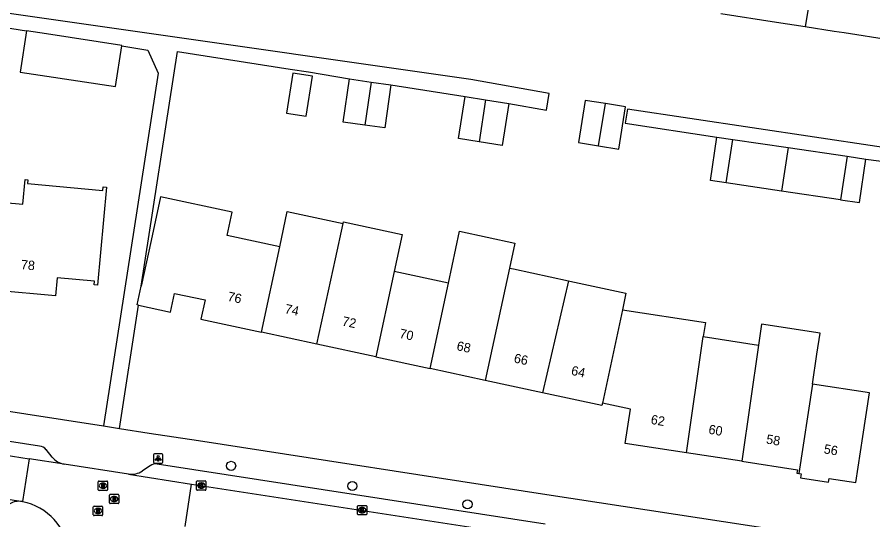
# Model space of a CAD drawing. Extents: x 161486 to 162249, y 379484 to 380829.
# Drawn here: x 161831.1 to 161923, y 380555.5 to 380609.4 of the extents above; entities that cross this region are included whole.
import ezdxf

# ---------------------------------------------------------------- set-up
doc = ezdxf.new("R2010")
doc.units = 0
for name, color, linetype in [('IMGEO_Boom', 7, 'Continuous'), ('IMGEO_Kolk', 7, 'Continuous'), ('IMGEO_Lichtpunt', 7, 'Continuous'), ('IMGEO_Pand', 7, 'Continuous'), ('IMGEO_Pand_nummerreeks', 7, 'Continuous'), ('IMGEO_Rijbaan_lokaal_open', 7, 'Continuous'), ('IMGEO_Rioolput', 7, 'Continuous'), ('IMGEO_Voetpad_open', 7, 'Continuous')]:
    doc.layers.add(name, color=color, linetype=linetype)

msp = doc.modelspace()

# ---------------------------------------------------------------- linework, layer by layer
at = {"layer": 'IMGEO_Boom'}
for centre in [(161854.107, 380561.287), (161867.109, 380559.125), (161879.472, 380557.176)]:
    msp.add_circle(centre, 0.489, dxfattribs=at)
at = {"layer": 'IMGEO_Kolk'}
for p, q in [((161850.484, 380559.678), (161851.336, 380559.678)), ((161850.409, 380558.752), (161850.409, 380559.604)), ((161850.92, 380558.898), (161850.895, 380558.898)), ((161850.897, 380559.458), (161850.922, 380559.458)), ((161851.41, 380559.604), (161851.41, 380558.752)), ((161851.336, 380558.678), (161850.484, 380558.678)), ((161867.662, 380556.114), (161867.662, 380556.966)), ((161867.737, 380557.04), (161868.589, 380557.04)), ((161868.663, 380556.966), (161868.663, 380556.114)), ((161868.589, 380556.04), (161867.737, 380556.04)), ((161868.173, 380556.26), (161868.148, 380556.26)), ((161868.15, 380556.82), (161868.175, 380556.82))]:
    msp.add_line(p, q, dxfattribs=at)
for points in [[(161850.484, 380559.678), (161851.336, 380559.678)], [(161850.409, 380558.752), (161850.409, 380559.604)], [(161850.73, 380559.378), (161850.853, 380559.378), (161850.853, 380559.227), (161850.983, 380559.378), (161851.147, 380559.378), (161851.001, 380559.227), (161851.154, 380558.978), (161851.002, 380558.978), (161850.917, 380559.142), (161850.853, 380559.075), (161850.853, 380558.978), (161850.73, 380558.978), (161850.73, 380559.378)], [(161851.41, 380559.604), (161851.41, 380558.752)], [(161851.336, 380558.678), (161850.484, 380558.678)], [(161867.662, 380556.114), (161867.662, 380556.966)], [(161867.737, 380557.04), (161868.589, 380557.04)], [(161868.663, 380556.966), (161868.663, 380556.114)], [(161868.589, 380556.04), (161867.737, 380556.04)], [(161867.983, 380556.74), (161868.106, 380556.74), (161868.106, 380556.589), (161868.236, 380556.74), (161868.4, 380556.74), (161868.254, 380556.589), (161868.407, 380556.34), (161868.255, 380556.34), (161868.17, 380556.504), (161868.106, 380556.437), (161868.106, 380556.34), (161867.983, 380556.34), (161867.983, 380556.74)]]:
    msp.add_lwpolyline(points, dxfattribs=at)
for centre, start, end in [((161850.486, 380559.602), 91.55205, 178.44795), ((161850.486, 380559.602), 91.55205, 178.44795), ((161851.334, 380559.602), 1.55205, 88.44795), ((161851.334, 380559.602), 1.55205, 88.44795), ((161850.486, 380558.754), 181.55205, 268.44795), ((161850.486, 380558.754), 181.55205, 268.44795), ((161851.334, 380558.754), 271.55205, 358.44795), ((161851.334, 380558.754), 271.55205, 358.44795), ((161867.739, 380556.964), 91.55205, 178.44795), ((161867.739, 380556.964), 91.55205, 178.44795), ((161868.587, 380556.964), 1.55205, 88.44795), ((161868.587, 380556.964), 1.55205, 88.44795), ((161867.739, 380556.116), 181.55205, 268.44795), ((161867.739, 380556.116), 181.55205, 268.44795), ((161868.587, 380556.116), 271.55205, 358.44795), ((161868.587, 380556.116), 271.55205, 358.44795)]:
    msp.add_arc(centre, 0.0765, start, end, dxfattribs=at)
for centre, major_axis, ratio, start_param, end_param in [((161850.896, 380559.178), (-0.387, 0.002), 0.722429, 4.712389, 7.853982), ((161850.921, 380559.178), (-0.39, 0.002), 0.717154, 1.570796, 4.712389), ((161868.149, 380556.54), (-0.387, 0.002), 0.722429, 4.712389, 7.853982), ((161868.174, 380556.54), (-0.39, 0.002), 0.717154, 1.570796, 4.712389)]:
    msp.add_ellipse(centre, major_axis=major_axis, ratio=ratio, start_param=start_param, end_param=end_param, dxfattribs=at)
at = {"layer": 'IMGEO_Lichtpunt'}
for p, q in [((161845.782, 380562.487), (161845.782, 380561.68)), ((161845.782, 380562.487), (161845.782, 380561.68)), ((161846.684, 380562.582), (161845.876, 380562.582)), ((161846.684, 380562.582), (161845.876, 380562.582)), ((161846.778, 380561.68), (161846.778, 380562.487)), ((161846.778, 380561.68), (161846.778, 380562.487)), ((161845.876, 380561.586), (161846.684, 380561.586)), ((161845.876, 380561.586), (161846.684, 380561.586))]:
    msp.add_line(p, q, dxfattribs=at)
for points in [[(161846.156, 380562.151), (161846.195, 380562.123), (161846.007, 380561.861), (161845.969, 380561.888), (161846.156, 380562.151)], [(161846.258, 380562.103), (161846.305, 380562.103), (161846.305, 380561.781), (161846.258, 380561.781), (161846.258, 380562.103)], [(161846.368, 380562.123), (161846.406, 380562.15), (161846.593, 380561.888), (161846.554, 380561.86), (161846.368, 380562.123)]]:
    msp.add_lwpolyline(points, dxfattribs=at)
msp.add_circle((161846.281, 380562.285), 0.0994, dxfattribs=at)
for centre, start, end in [((161845.876, 380562.487), 90, 180), ((161845.876, 380562.487), 90, 180), ((161846.684, 380562.487), 0, 90), ((161846.684, 380562.487), 0, 90), ((161845.876, 380561.68), 180, 270), ((161845.876, 380561.68), 180, 270), ((161846.684, 380561.68), 270, 0), ((161846.684, 380561.68), 270, 360)]:
    msp.add_arc(centre, 0.0946, start, end, dxfattribs=at)
at = {"layer": 'IMGEO_Pand'}
for points in [[(161917.716, 380621.282), (161923.826, 380620.34), (161923.776, 380620.014), (161923.448, 380620.062), (161922.489, 380614.014), (161925.86, 380613.48), (161924.84, 380606.93), (161919.899, 380607.691), (161918.824, 380607.857), (161915.718, 380608.336)], [(161917.716, 380621.282), (161916.158, 380611.186), (161915.718, 380608.336)], [(161915.718, 380608.336), (161912.612, 380608.815), (161906.646, 380609.735)], [(161832.16, 380607.936), (161831.481, 380603.508), (161833.607, 380603.182), (161841.714, 380601.939), (161842.385, 380606.316)], [(161842.385, 380606.316), (161842.393, 380606.367), (161834.286, 380607.61), (161832.16, 380607.936)], [(161862.174, 380598.776), (161862.854, 380603.062), (161860.742, 380603.397), (161860.062, 380599.111), (161862.174, 380598.776)], [(161868.445, 380597.821), (161866.145, 380598.149), (161866.804, 380602.759)], [(161866.804, 380602.759), (161869.142, 380602.425)], [(161869.142, 380602.425), (161868.445, 380597.821)], [(161871.255, 380602.123), (161870.597, 380597.514), (161868.445, 380597.821)], [(161869.142, 380602.425), (161871.255, 380602.123)], [(161880.721, 380596.031), (161878.51, 380596.383), (161879.224, 380600.868)], [(161879.224, 380600.868), (161881.401, 380600.521)], [(161881.401, 380600.521), (161880.721, 380596.031)], [(161883.887, 380600.126), (161883.173, 380595.641), (161880.721, 380596.031)], [(161881.401, 380600.521), (161883.887, 380600.126)], [(161894.269, 380600.119), (161892.108, 380600.468), (161891.377, 380595.94), (161893.538, 380595.591)], [(161893.538, 380595.591), (161894.269, 380600.119)], [(161893.538, 380595.591), (161895.698, 380595.242), (161896.429, 380599.77), (161894.269, 380600.119)], [(161907.228, 380591.616), (161905.531, 380591.864), (161906.212, 380596.519)], [(161906.212, 380596.519), (161907.933, 380596.268)], [(161907.228, 380591.616), (161907.933, 380596.268)], [(161907.933, 380596.268), (161913.867, 380595.4)], [(161913.867, 380595.4), (161913.174, 380590.746)], [(161913.867, 380595.4), (161920.206, 380594.472)], [(161920.206, 380594.472), (161919.495, 380589.821)], [(161919.495, 380589.821), (161921.545, 380589.521), (161922.227, 380594.176)], [(161920.206, 380594.472), (161922.227, 380594.176)], [(161829.752, 380589.535), (161831.766, 380589.35), (161832.008, 380591.981), (161832.306, 380591.954), (161832.27, 380591.555), (161840.35, 380590.812), (161840.386, 380591.21), (161840.745, 380591.177), (161839.777, 380580.662), (161839.419, 380580.695), (161839.455, 380581.088), (161835.427, 380581.459), (161835.248, 380579.514), (161828.883, 380580.1)], [(161913.174, 380590.746), (161907.228, 380591.616)], [(161859.317, 380584.764), (161853.676, 380585.979), (161854.213, 380588.471), (161846.529, 380590.126), (161845.518, 380585.433), (161844.465, 380580.545)], [(161919.495, 380589.821), (161913.174, 380590.746)], [(161859.317, 380584.764), (161860.136, 380588.564), (161866.129, 380587.273)], [(161863.308, 380574.344), (161865.301, 380583.475), (161866.129, 380587.273)], [(161866.129, 380587.273), (161866.164, 380587.432), (161872.458, 380586.077), (161871.605, 380582.117)], [(161877.415, 380580.866), (161878.615, 380586.438), (161884.547, 380585.161), (161883.971, 380582.483)], [(161857.349, 380575.628), (161859.317, 380584.764)], [(161871.605, 380582.117), (161869.638, 380572.981)], [(161877.415, 380580.866), (161871.605, 380582.117)], [(161883.971, 380582.483), (161881.377, 380570.452)], [(161883.971, 380582.483), (161884.39, 380582.393), (161890.304, 380581.119)], [(161875.476, 380571.723), (161877.415, 380580.866)], [(161890.304, 380581.119), (161887.511, 380569.131)], [(161890.304, 380581.119), (161890.462, 380581.085), (161896.472, 380579.79), (161896.089, 380578.009)], [(161844.153, 380578.524), (161844.035, 380578.549), (161844.465, 380580.545)], [(161844.153, 380578.524), (161847.611, 380577.779), (161848.041, 380579.775), (161851.308, 380579.071), (161850.867, 380577.024), (161857.349, 380575.628)], [(161896.089, 380578.009), (161893.937, 380568.018)], [(161896.089, 380578.009), (161904.995, 380576.648), (161904.771, 380575.144)], [(161916.475, 380570.046), (161916.969, 380573.28), (161917.312, 380575.528), (161911.019, 380576.489), (161910.697, 380574.238)], [(161863.308, 380574.344), (161857.349, 380575.628)], [(161902.969, 380562.694), (161904.771, 380575.144)], [(161904.771, 380575.144), (161910.697, 380574.238)], [(161869.638, 380572.981), (161863.308, 380574.344)], [(161910.697, 380574.238), (161908.915, 380561.786)], [(161869.638, 380572.981), (161875.476, 380571.723)], [(161881.377, 380570.452), (161875.476, 380571.723)], [(161887.511, 380569.131), (161881.377, 380570.452)], [(161915.011, 380560.46), (161915.269, 380560.421), (161915.204, 380559.997), (161918.204, 380559.538), (161918.264, 380559.931), (161921.134, 380559.493), (161921.89, 380564.436), (161922.604, 380569.109), (161916.475, 380570.046)], [(161916.475, 380570.046), (161915.011, 380560.46)], [(161893.937, 380568.018), (161893.881, 380567.759), (161887.511, 380569.131)], [(161902.969, 380562.694), (161896.392, 380563.699), (161896.948, 380567.369), (161893.937, 380568.018)], [(161908.915, 380561.786), (161902.969, 380562.694)], [(161908.915, 380561.786), (161914.881, 380560.874), (161914.822, 380560.489), (161915.011, 380560.46)]]:
    msp.add_lwpolyline(points, dxfattribs=at)
at = {"layer": 'IMGEO_Rijbaan_lokaal_open'}
for points in [[(161831.511, 380557.484), (161829.252, 380557.84), (161786.826, 380564.413), (161764.174, 380567.941)], [(161791.712, 380568.325), (161795.116, 380567.782), (161814.963, 380564.744), (161829.769, 380562.474), (161832.422, 380562.046)], [(161832.422, 380562.046), (161831.714, 380557.452)], [(161836.189, 380561.463), (161832.422, 380562.046)], [(161843.094, 380560.41), (161836.189, 380561.463)], [(161843.094, 380560.41), (161849.846, 380559.342)], [(161849.159, 380554.782), (161849.846, 380559.342)], [(161849.846, 380559.342), (161887.499, 380553.536), (161890.424, 380553.087)], [(161831.714, 380557.452), (161831.511, 380557.484)]]:
    msp.add_lwpolyline(points, dxfattribs=at)
msp.add_arc((161830.522, 380551.353), 6.214, 5.48219, 78.94489, dxfattribs=at)
at = {"layer": 'IMGEO_Rioolput'}
for p, q in [((161839.856, 380558.733), (161839.856, 380559.585)), ((161839.931, 380559.659), (161840.783, 380559.659)), ((161840.367, 380558.879), (161840.342, 380558.879)), ((161840.344, 380559.439), (161840.369, 380559.439)), ((161840.857, 380559.585), (161840.857, 380558.733)), ((161840.783, 380558.659), (161839.931, 380558.659)), ((161841.06, 380557.312), (161841.06, 380558.164)), ((161841.135, 380558.238), (161841.987, 380558.238)), ((161841.548, 380558.018), (161841.573, 380558.018)), ((161842.061, 380558.164), (161842.061, 380557.312)), ((161839.397, 380556.964), (161840.249, 380556.964)), ((161841.987, 380557.238), (161841.135, 380557.238)), ((161841.571, 380557.458), (161841.546, 380557.458)), ((161839.322, 380556.038), (161839.322, 380556.89)), ((161839.833, 380556.184), (161839.808, 380556.184)), ((161839.81, 380556.744), (161839.835, 380556.744)), ((161840.323, 380556.89), (161840.323, 380556.038)), ((161840.249, 380555.964), (161839.397, 380555.964))]:
    msp.add_line(p, q, dxfattribs=at)
for points in [[(161839.856, 380558.733), (161839.856, 380559.585)], [(161839.931, 380559.659), (161840.783, 380559.659)], [(161840.445, 380559.357), (161840.193, 380559.359), (161840.193, 380558.959)], [(161840.193, 380558.959), (161840.317, 380558.959), (161840.317, 380559.121), (161840.328, 380559.121)], [(161840.371, 380559.278), (161840.317, 380559.278), (161840.317, 380559.197)], [(161840.317, 380559.197), (161840.369, 380559.197)], [(161840.375, 380559.092), (161840.446, 380558.959), (161840.586, 380558.959), (161840.521, 380559.085)], [(161840.857, 380559.585), (161840.857, 380558.733)], [(161840.783, 380558.659), (161839.931, 380558.659)], [(161841.06, 380557.312), (161841.06, 380558.164)], [(161841.135, 380558.238), (161841.987, 380558.238)], [(161841.649, 380557.936), (161841.397, 380557.938), (161841.397, 380557.538)], [(161841.575, 380557.857), (161841.521, 380557.857), (161841.521, 380557.776)], [(161842.061, 380558.164), (161842.061, 380557.312)], [(161839.397, 380556.964), (161840.249, 380556.964)], [(161841.987, 380557.238), (161841.135, 380557.238)], [(161841.397, 380557.538), (161841.521, 380557.538), (161841.521, 380557.7), (161841.532, 380557.7)], [(161841.521, 380557.776), (161841.573, 380557.776)], [(161841.579, 380557.671), (161841.65, 380557.538), (161841.79, 380557.538), (161841.725, 380557.664)], [(161839.322, 380556.038), (161839.322, 380556.89)], [(161839.911, 380556.662), (161839.659, 380556.664), (161839.659, 380556.264)], [(161839.659, 380556.264), (161839.783, 380556.264), (161839.783, 380556.426), (161839.794, 380556.426)], [(161839.837, 380556.583), (161839.783, 380556.583), (161839.783, 380556.502)], [(161839.783, 380556.502), (161839.835, 380556.502)], [(161839.841, 380556.397), (161839.912, 380556.264), (161840.052, 380556.264), (161839.987, 380556.39)], [(161840.323, 380556.89), (161840.323, 380556.038)], [(161840.249, 380555.964), (161839.397, 380555.964)]]:
    msp.add_lwpolyline(points, dxfattribs=at)
for centre, radius, start, end in [((161839.933, 380559.583), 0.0765, 91.55205, 178.44795), ((161839.933, 380559.583), 0.0765, 91.55205, 178.44795), ((161840.327, 380559.068), 0.0533, 26.02933, 88.69889), ((161840.353, 380559.386), 0.19, 274.7715, 282.96867), ((161840.377, 380559.182), 0.0964, 77.00612, 93.18647), ((161840.391, 380559.239), 0.0378, 276.66336, 79.67722), ((161840.444, 380559.247), 0.109, 350.36119, 89.41601), ((161840.442, 380559.247), 0.112, 277.58423, 350.98172), ((161840.426, 380559.032), 0.108, 29.51342, 73.79051), ((161840.781, 380559.583), 0.0765, 1.55205, 88.44795), ((161840.781, 380559.583), 0.0765, 1.55205, 88.44795), ((161839.933, 380558.735), 0.0765, 181.55205, 268.44795), ((161839.933, 380558.735), 0.0765, 181.55205, 268.44795), ((161840.781, 380558.735), 0.0765, 271.55205, 358.44795), ((161840.781, 380558.735), 0.0765, 271.55205, 358.44795), ((161841.137, 380558.162), 0.0765, 91.55205, 178.44795), ((161841.137, 380558.162), 0.0765, 91.55205, 178.44795), ((161841.581, 380557.761), 0.0964, 77.00612, 93.18647), ((161841.595, 380557.818), 0.0378, 276.66336, 79.67722), ((161841.648, 380557.826), 0.109, 350.36119, 89.41601), ((161841.985, 380558.162), 0.0765, 1.55205, 88.44795), ((161841.985, 380558.162), 0.0765, 1.55205, 88.44795), ((161839.399, 380556.888), 0.0765, 91.55205, 178.44795), ((161839.399, 380556.888), 0.0765, 91.55205, 178.44795), ((161840.247, 380556.888), 0.0765, 1.55205, 88.44795), ((161840.247, 380556.888), 0.0765, 1.55205, 88.44795), ((161841.137, 380557.314), 0.0765, 181.55205, 268.44795), ((161841.137, 380557.314), 0.0765, 181.55205, 268.44795), ((161841.531, 380557.647), 0.0533, 26.02933, 88.69889), ((161841.557, 380557.965), 0.19, 274.7715, 282.96867), ((161841.646, 380557.826), 0.112, 277.58423, 350.98172), ((161841.63, 380557.611), 0.108, 29.51342, 73.79051), ((161841.985, 380557.314), 0.0765, 271.55205, 358.44795), ((161841.985, 380557.314), 0.0765, 271.55205, 358.44795), ((161839.399, 380556.04), 0.0765, 181.55205, 268.44795), ((161839.399, 380556.04), 0.0765, 181.55205, 268.44795), ((161839.793, 380556.373), 0.0533, 26.02933, 88.69889), ((161839.819, 380556.691), 0.19, 274.7715, 282.96867), ((161839.843, 380556.487), 0.0964, 77.00612, 93.18647), ((161839.857, 380556.544), 0.0378, 276.66336, 79.67722), ((161839.91, 380556.552), 0.109, 350.36119, 89.41601), ((161839.908, 380556.552), 0.112, 277.58423, 350.98172), ((161839.892, 380556.337), 0.108, 29.51342, 73.79051), ((161840.247, 380556.04), 0.0765, 271.55205, 358.44795), ((161840.247, 380556.04), 0.0765, 271.55205, 358.44795)]:
    msp.add_arc(centre, radius, start, end, dxfattribs=at)
for centre, major_axis, ratio, start_param, end_param in [((161840.343, 380559.159), (-0.387, 0.002), 0.722429, 4.712389, 7.853982), ((161840.368, 380559.159), (-0.39, 0.002), 0.717154, 1.570796, 4.712389), ((161841.547, 380557.738), (-0.387, 0.002), 0.722429, 4.712389, 7.853982), ((161841.572, 380557.738), (-0.39, 0.002), 0.717154, 1.570796, 4.712389), ((161839.809, 380556.464), (-0.387, 0.002), 0.722429, 4.712389, 7.853982), ((161839.834, 380556.464), (-0.39, 0.002), 0.717154, 1.570796, 4.712389)]:
    msp.add_ellipse(centre, major_axis=major_axis, ratio=ratio, start_param=start_param, end_param=end_param, dxfattribs=at)
at = {"layer": 'IMGEO_Voetpad_open'}
for points in [[(161883.887, 380600.126), (161887.936, 380599.416), (161888.243, 380601.193), (161879.814, 380602.708), (161803.016, 380613.72)], [(161827.864, 380608.608), (161832.16, 380607.936)], [(161842.385, 380606.316), (161845.162, 380605.856), (161846.266, 380603.381), (161840.43, 380565.564)], [(161844.465, 380580.545), (161848.361, 380605.693), (161860.44, 380603.822), (161862.401, 380603.511), (161866.804, 380602.759)], [(161871.255, 380602.123), (161879.224, 380600.868)], [(161930.073, 380594.51), (161896.647, 380599.526), (161896.401, 380598.035), (161906.212, 380596.519)], [(161922.227, 380594.176), (161923.617, 380593.973), (161926.255, 380593.587)], [(161759.209, 380578.08), (161759.686, 380578.007), (161785.522, 380574.037), (161840.43, 380565.564)], [(161842.113, 380565.304), (161844.153, 380578.524)], [(161833.563, 380563.394), (161794.647, 380569.433)], [(161840.43, 380565.564), (161842.113, 380565.304)], [(161842.113, 380565.304), (161845.302, 380564.812), (161850.616, 380563.993), (161887.994, 380558.235), (161920.738, 380553.21), (161923.744, 380552.759)], [(161834.914, 380562.21), (161834.252, 380563.026)], [(161845.417, 380561.299), (161844.603, 380560.74)], [(161887.795, 380555.038), (161850.1, 380560.875), (161846.172, 380561.483)]]:
    msp.add_lwpolyline(points, dxfattribs=at)
for centre, radius, start, end in [((161833.506, 380562.458), 0.937, 37.27058, 86.51541), ((161836.574, 380563.582), 2.154, 219.57402, 259.69541), ((161843.399, 380562.631), 2.242, 262.18811, 302.48327), ((161846.005, 380560.529), 0.968, 80.04035, 127.35261), ((161831.319, 380555.611), 1.882, 84.15465, 126.22171)]:
    msp.add_arc(centre, radius, start, end, dxfattribs=at)

# ---------------------------------------------------------------- texts
at = {"layer": 'IMGEO_Pand_nummerreeks'}
for s, rotation, p in [('78', 354.74025, (161831.523, 380582.386)), ('76', 347.84184, (161853.662, 380579)), ('74', 347.84184, (161859.807, 380577.677)), ('72', 347.84184, (161865.949, 380576.354)), ('70', 347.84449, (161872.1, 380575.028)), ('68', 347.84449, (161878.244, 380573.705)), ('66', 347.84449, (161884.386, 380572.382)), ('64', 347.84449, (161890.531, 380571.059)), ('62', 350.35193, (161899.084, 380565.797)), ('60', 350.35193, (161905.277, 380564.744)), ('58', 350.35139, (161911.465, 380563.693)), ('56', 350.35193, (161917.648, 380562.642))]:
    msp.add_text(s, height=1, rotation=rotation, dxfattribs=at).set_placement(p)

doc.saveas('drawing.dxf')
